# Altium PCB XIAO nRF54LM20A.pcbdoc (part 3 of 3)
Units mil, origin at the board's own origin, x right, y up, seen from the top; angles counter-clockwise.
Board outline 1393.7 x 1456.69 mil, 6 copper layers (Top Layer, L2.Cu, L3.Cu, L4.Cu, L5.Cu, Bottom Layer), stack 1.58 mil thick; 146 components, 0 nets, 519 pads, 402 vias.
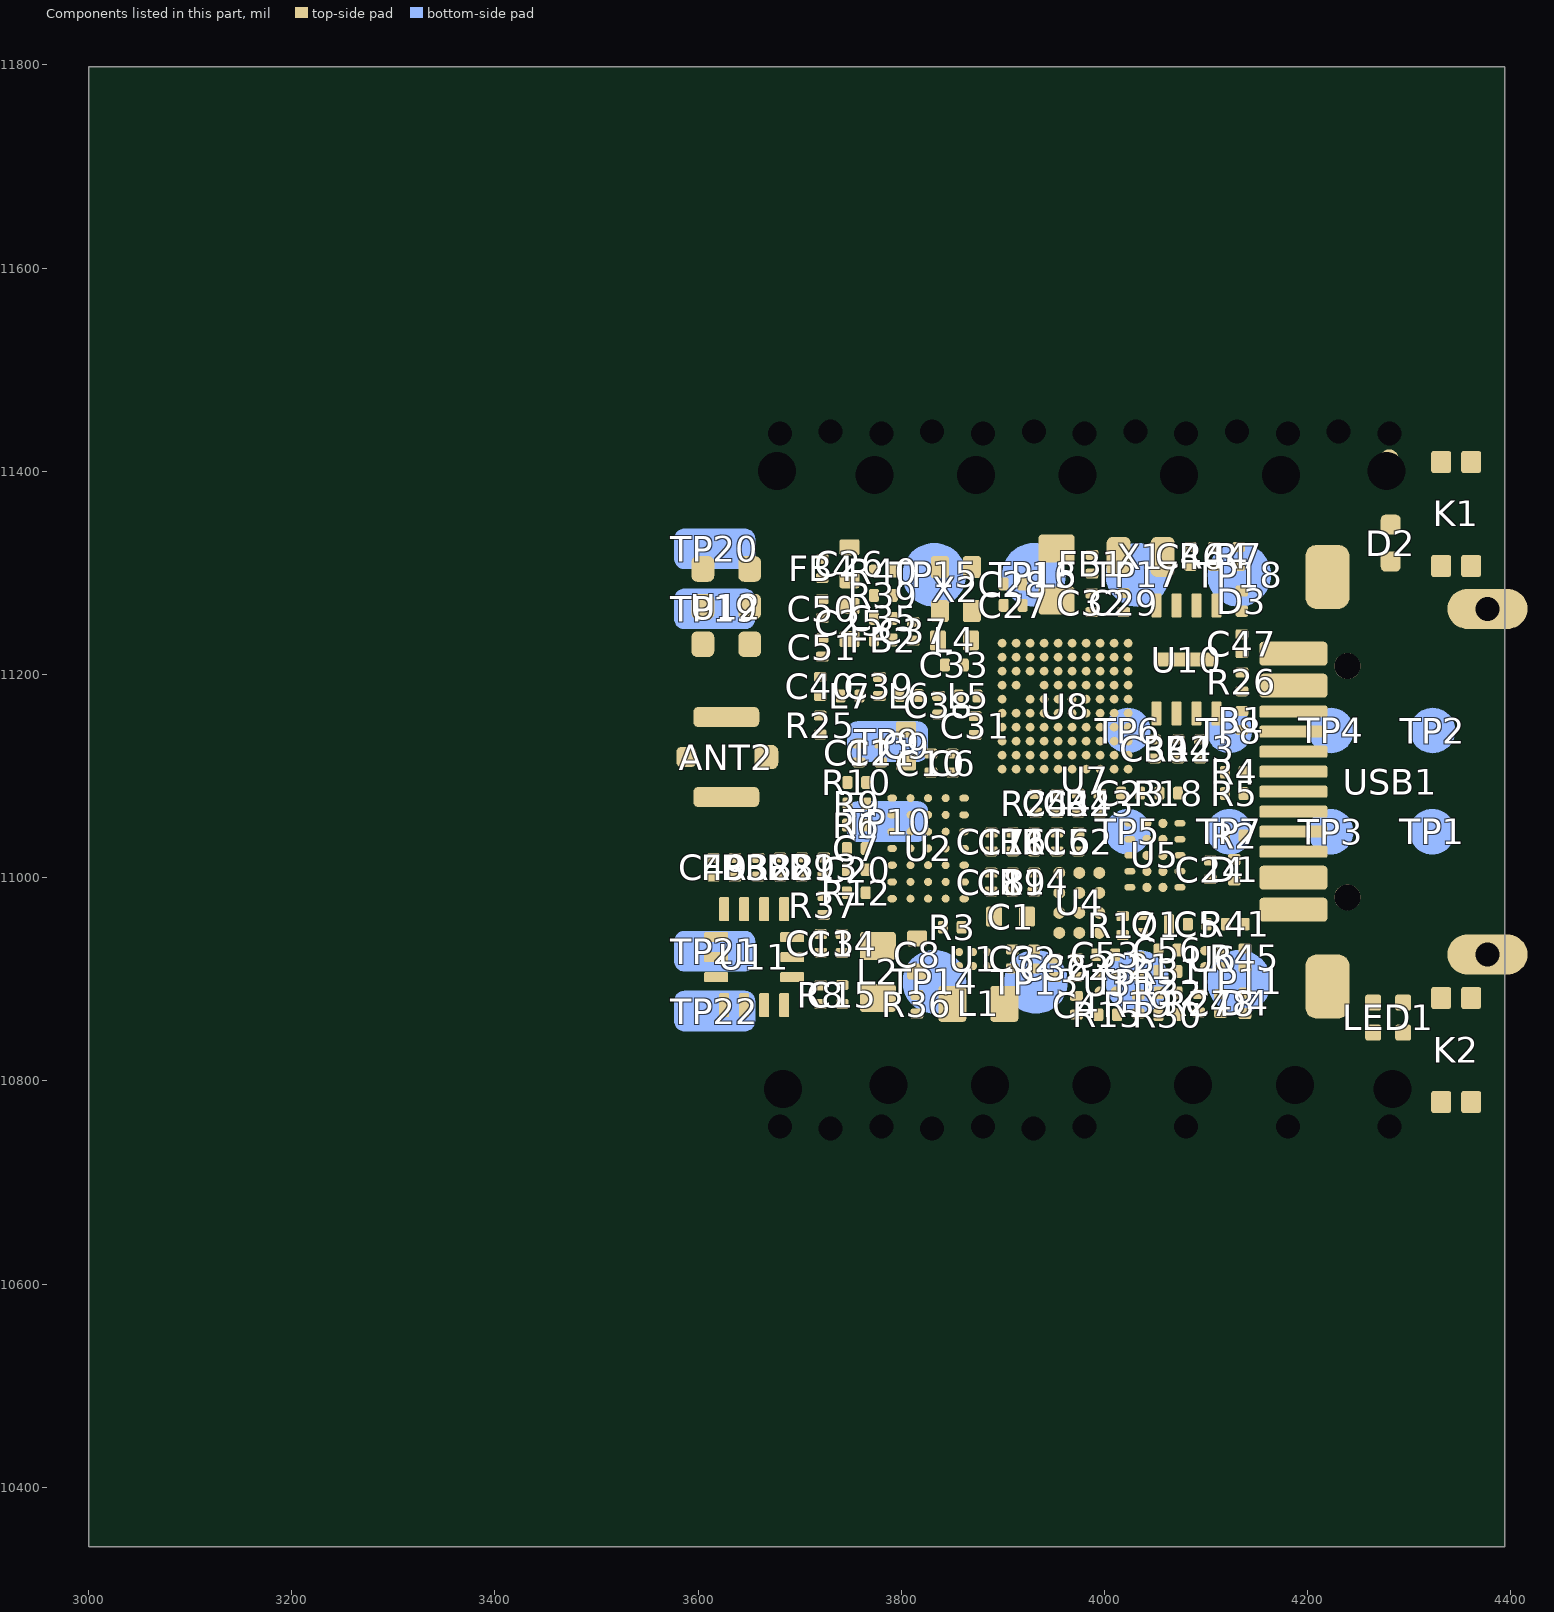
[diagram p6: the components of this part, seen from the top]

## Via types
v1: diameter 10, hole 6, Top Layer to Bottom Layer, 210 vias
v2: diameter 8, hole 4, Top Layer to L2.Cu, 76 vias
v3: diameter 10, hole 6, L3.Cu to L4.Cu, 47 vias
v4: diameter 8, hole 4, Top Layer to L3.Cu, 43 vias
v5: diameter 8, hole 4, L2.Cu to L3.Cu, 20 vias
v6: diameter 8, hole 4, L4.Cu to Bottom Layer, 6 vias

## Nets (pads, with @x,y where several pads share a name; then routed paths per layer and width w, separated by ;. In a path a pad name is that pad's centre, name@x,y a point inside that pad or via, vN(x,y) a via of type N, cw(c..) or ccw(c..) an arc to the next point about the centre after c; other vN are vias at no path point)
pads on no net: ANT2.1 ANT2.2 ANT2.3 ANT2.4 C1.1 C1.2 C2.1 C2.2 C3.1 C3.2 C4.1 C4.2 C5.1 C5.2 C6.1 C6.2 C7.1 C7.2 C8.1 C8.2 C9.1 C9.2 C10.1 C10.2 C11.1 C11.2 C12.1 C12.2 C13.1 C13.2 C14.1 C14.2 C15.1 C15.2 C16.1 C16.2 C17.1 C17.2 C18.1 C18.2 C19.1 C19.2 C20.1 C20.2 C21.1 C21.2 C22.1 C22.2 C23.1 C23.2 C24.1 C24.2 C25.1 C25.2 C26.1 C26.2 C27.1 C27.2 C28.1 C28.2 C29.1 C29.2 C30.1 C30.2 C31.1 C31.2 C32.1 C32.2 C33.1 C33.2 C34.1 C34.2 C35.1 C35.2 C36.1 C36.2 C37.1 C37.2 C38.1 C38.2 C39.1 C39.2 C40.1 C40.2 C46.1 C46.2 C47.1 C47.2 C48.1 C48.2 C49.1 C49.2 C50.1 C50.2 C51.1 C51.2 C52.1 C52.2 C53.1 C53.2 C54.1 C54.2 C56.1 C56.2 D1.1 D1.2 D2.1 D2.2 D3.1 D3.2 D4.1 D4.2 FB1.1 FB1.2 FB2.1 FB2.2 FB3.1 FB3.2 FB4.1 FB4.2 K1.1 K1.2 K1.3 K1.4 K2.1 K2.2 K2.3 K2.4 L1.1 L1.2 L2.1 L2.2 L3.1 L3.2 L4.1 L4.2 L5.1 L5.2 L6.1 L6.2 L7.1 L7.2 LED1.1 LED1.2 LED1.3 LED1.4 Q1.1 Q1.2 Q1.3 R1.1 R1.2 R2.1 R2.2 R3.1 R3.2 R4.1 R4.2 R5.1 R5.2 R6.1 R6.2 R7.1 R7.2 R8.1 R8.2 R9.1 R9.2 R10.1 R10.2 R11.1 R11.2 R12.1 R12.2 R13.1 R13.2 R14.1 R14.2 R15.1 R15.2 R16.1 R16.2 R17.1 R17.2 R18.1 R18.2 R19.1 R19.2 R23.1 R23.2 R24.1 R24.2 R25.1 R25.2 R26.1 R26.2 R27.1 R27.2 R28.1 R28.2 R29.1 R29.2 R30.1 R30.2 R31.1 R31.2 R32.1 R32.2 R36.1 R36.2 R37.1 R37.2 R38.1 R38.2 R39.1 R39.2 R40.1 R40.2 R41.1 R41.2 R42.1 R42.2 R43.1 R43.2 R44.1 R44.2 R45.1 R45.2 TP1.1 TP2.1 TP3.1 TP4.1 TP5.1 TP6.1 TP7.1 TP8.1 TP9.1 TP10.1 TP11.1 TP12.1 TP13.1 TP14.1 TP15.1 TP16.1 TP17.1 TP18.1 TP19.1 TP20.1 TP21.1 TP22.1 U1.A1 U1.A2 U1.B1 U1.B2 U1.C1 U1.C2 U2.A1 U2.A2 U2.A3 U2.A4 U2.A5 U2.A6 U2.A7 U2.B1 U2.B2 U2.B3 U2.B4 U2.B5 U2.B6 U2.B7 U2.C1 U2.C2 U2.C3 U2.C4 U2.C5 U2.C6 U2.C7 U2.D1 U2.D2 U2.D3 U2.D4 U2.D5 U2.D6 U2.D7 U2.E1 U2.E2 U2.E3 U2.E4 U2.E5 U2.E6 U2.E7 U3.A1 U3.A2 U3.B1 U3.B2 U4.A1 U4.A2 U4.A3 U4.B1 U4.B2 U4.B3 U4.C1 U4.C2 U4.C3 U4.D1 U4.D2 U4.D3 U5.A1 U5.A2 U5.A3 U5.A4 U5.B1 U5.B2 U5.B3 U5.B4 U5.C1 U5.C2 U5.C3 U5.C4 U5.D1 U5.D2 U5.D3 U5.D4 U5.E1 U5.E2 U5.E3 U5.E4 U6.A1 U6.A2 U6.B1 U6.B2 U7.1 U7.2 U7.3 U7.4 U7.5 U7.6 U7.7 U7.8 U7.9 U7.10 U7.11 U7.12 U7.13 U7.14 U7.15 U7.16 U7.17 U7.18 U7.19 U7.20 U7.21 U7.22 U7.23 U8.A1 U8.A2 U8.A3 U8.A4 U8.A5 U8.A6 U8.A7 U8.A8 U8.A9 U8.A10 U8.B1 U8.B2 U8.B3 U8.B4 U8.B5 U8.B6 U8.B7 U8.B8 U8.B9 U8.B10 U8.C1 U8.C2 U8.C3 U8.C4 U8.C5 U8.C6 U8.C7 U8.C8 U8.C9 U8.C10 U8.D1 U8.D2 U8.D4 U8.D5 U8.D6 U8.D7 U8.D8 U8.D9 U8.D10 U8.E1 U8.E3 U8.E4 U8.E5 U8.E6 U8.E7 U8.E8 U8.E9 U8.E10 U8.F1 U8.F2 U8.F3 U8.F4 U8.F5 U8.F6 U8.F7 U8.F8 U8.F9 U8.F10 U8.G1 U8.G2 U8.G3 U8.G4 U8.G5 U8.G6 U8.G7 U8.G8 U8.G9 U8.G10 U8.H1 U8.H2 U8.H3 U8.H4 U8.H5 U8.H6 U8.H7 U8.H8 U8.H9 U8.H10 U8.J1 U8.J2 U8.J3 U8.J4 U8.J5 U8.J6 U8.J7 U8.J8 U8.J9 U8.J10 U8.K1 U8.K2 U8.K3 U8.K4 U8.K5 U8.K6 U8.K7 U8.K8 U8.K9 U8.K10 U10.1 U10.2 U10.3 U10.4 U10.5 U10.6 U10.7 U10.8 U10.9 U11.1 U11.2 U11.3 U11.4 U11.5 U11.6 U11.7 U11.8 U11.9 U11.10 U11.11 U11.12 U11.13 U11.14 U12.1 U12.2 U12.3 U12.4 U12.5 U12.6 USB1. USB1.A1B12 USB1.A4B9 USB1.A5 USB1.A6 USB1.A7 USB1.A8 USB1.B1A12 USB1.B4A9 USB1.B5 USB1.B6 USB1.B7 USB1.B8 USB1.S1 USB1.S2 USB1.S3 USB1.S4 X1.1 X1.2 X2.1 X2.2 X2.3 X2.4
copper on no net: | length 36443.2
  Top Layer w3: 6910.97,7346.9 6910.97,7361.13 6915.5,7365.66 6930.57,7365.66 6943.82,7378.91 6944.28,7378.91 ; 6965.92,7379.14 6988.46,7356.6 6988.46,7325.12 6982.69,7319.34 6977.9,7319.34 ; 6977.9,7299.66 6991.5,7299.66 6994.5,7302.66 6994.5,7372.03 6987.36,7379.17 ; 7009,7341.41 7011.55,7341.41 7017.8,7347.66 ; 7009,7397.91 7009,7406.66 7020.5,7418.16 7059,7418.16 7064.06,7423.22 7076.21,7423.22 ; 7030.5,7349.66 7040,7349.66 7050.25,7359.91 7050.25,7363.16 7050.25,7364.66 7075.82,7390.23 7076.21,7390.23 ; 7035,7645.16 7045.55,7655.71 7058.41,7655.71 ; 7035.9,7672.66 7037.4,7671.16 ; 7037.5,7671.16 7045.97,7679.63 7058.41,7679.63 ; 7050.39,7429.66 7052.32,7429.66 7053.96,7431.3 7086.23,7431.3 7094.32,7423.22 ; 7050.75,7450.66 7050.75,7448.63 7059.66,7439.71 7076.21,7439.71 ; 7050.75,7471.66 7050.75,7469.63 7064.17,7456.21 7076.21,7456.21 ; 7076.91,7655.71 7077.45,7655.71 7089,7644.16 ; 7100.64,7262.59 7108.16,7262.59 7136.51,7290.94 7142.22,7290.94 ; 7123.25,7683.56 7123.25,7681.91 7143,7662.16 7161.25,7662.16 7171.5,7651.91 7171.5,7635.56 7198.28,7608.78 ; 7142.22,7304.72 7142.22,7326.63 7144.75,7329.16 ; 7147.07,7439.71 7152.94,7439.71 ; 7154.75,7640.25 7170.5,7624.5 7170.5,7602.16 7177.66,7595 7184.5,7595 ; 7198.28,7539.88 7200,7541.6 7200,7555.32 7201.06,7556.38 ; 7209.36,7578.84 7211.46,7578.84 7212.06,7579.44 7212.06,7581.22 ; 7217.5,7460.41 7217.5,7466.26 7224.51,7473.27 7224.51,7473.45 7225.9,7472.06 ; 7219,7567.16 7219.28,7567.44 7225.84,7567.44 ; 7280.12,7323.6 7290.57,7334.05 7290.57,7373.22 7301.5,7384.16 7310.26,7384.16 ; 7296.03,7266.09 7315.13,7266.09 7318.52,7262.69 7317.41,7262.69 7297.65,7242.94 ; 7303.21,7340.03 7304.2,7339.05 7323.2,7339.05 7327,7342.85 7327,7368.41 ; 7308.52,7539.88 7311.22,7539.88 7328.5,7557.16 7352,7557.16 7355.66,7553.5 7355.66,7540.01 7356.16,7539.51 ; 7308.52,7553.66 7316,7553.66 7326,7563.66 7367.5,7563.66 7375.34,7555.81 7375.34,7540.01 7375.84,7539.51 7375.34,7539.01 7375.34,7518.07 7379.5,7513.91 ; 7308.52,7567.44 7318.28,7567.44 7329,7578.16 7329,7600.16 7341,7612.16 7370.49,7612.16 7370.69,7612.36 7389.2,7612.36 7395.03,7618.19 7395.03,7645.31 7395.53,7645.81 ; 7308.52,7581.22 7318.02,7581.22 7322.96,7586.16 7322.96,7603.12 7338,7618.16 7368,7618.16 7375.34,7625.5 7375.34,7645.31 7375.84,7645.81 ; 7308.52,7595 7316.92,7603.4 7316.92,7605.62 7335.76,7624.46 7351.4,7624.46 7356.16,7629.22 7356.16,7645.81 7356.16,7652.81 7388.25,7684.91 7393.5,7684.91 ; 7320.25,7461.16 7339.25,7461.16 7342.75,7457.65 7342.75,7431.4 ; 7331.5,7235.66 7338.5,7242.66 7338.5,7243.16 ; 7336.47,7539.51 7335.97,7539.01 7335.97,7533.19 7355.25,7513.91 7358,7513.91 ; 7348.47,7357.26 7348.47,7353.78 7348.8,7353.45 7348.8,7332.16 ; 7357,7243.16 7362.5,7248.66 ; 7359.5,7431.4 7359.5,7441.16 ; 7378,7263.66 7378.25,7263.41 7399.5,7263.41 7400.28,7264.19 7423.5,7264.19 7423.5,7265.66 7447.5,7289.66 7469.5,7311.66 7564.57,7311.66 7616.69,7259.54 7646.21,7259.54 ; 7399.87,7290.28 7402.63,7290.28 7420.75,7308.41 7423.5,7308.41 7423.5,7331.91 7423.25,7332.16 ; 7417.5,7703.41 7432.5,7688.41 7432.5,7681.66 7432.5,7643.16 7443.5,7632.16 7553.5,7632.16 7586,7664.66 7586,7706.37 7567,7725.37 ; 7420.5,7541.91 7421.15,7541.26 7471.26,7541.26 ; 7420.5,7579.91 7420.5,7597.66 7411,7597.66 7405,7603.66 7405,7625.16 7419.97,7640.13 7420.5,7640.13 7421.03,7640.13 7437,7624.16 7556.5,7624.16 7616.69,7684.34 7616.69,7684.73 7646.21,7684.73 ; 7420.5,7703.41 7422.25,7703.41 ; 7422.25,7419.16 7426.25,7423.15 7471.26,7423.15 ; 7549.5,7688.66 7549.79,7688.95 7567,7688.95 ; 7549.74,7254.92 7549.74,7274.49
  Top Layer w4: 7211.76,7610.06 7212.06,7609.76
  Top Layer w5.59: 4136.95,11082.7 cw(c4141.46,11078.2) 4141.46,11084.57 ; 4136.95,11103.7 cw(c4138.28,11102.37) 4138.28,11104.26 ; 7359.5,7399.91 7365.01,7399.91 7367.09,7401.98 7376.79,7401.98 7388.1,7413.3 7388.1,7460.43 7393.03,7465.36 7397.67,7465.36 7402.37,7460.66 7403.75,7460.66 ; 7359.5,7415.65 7365.01,7415.65 7367.09,7413.57 7371.99,7413.57 7376.51,7418.1 7376.51,7465.16 7388.31,7476.95 7397.67,7476.95 7402.37,7481.66 7403.75,7481.66 ; 7423.58,7482.21 7471.26,7482.21 7507.45,7482.21 7512,7477.66 7512,7447.66 7507.18,7442.84 7471.26,7442.84 ; 7426.76,7462.52 7471.26,7462.52
  Top Layer w6: 7050.25,7385.66 7071.32,7406.72 7076.21,7406.72 ; 7070.5,7353.66 7074.08,7357.23 7076.21,7357.23 ; 7147.07,7406.72 7149.83,7406.72 7173.68,7382.87 ; 7236.5,7298.91 7236.66,7298.91 7255.16,7280.41 7257.5,7280.41 ; 7359.5,7384.16 7366,7384.16 7373.75,7376.41 7392,7376.41
  Top Layer w6.16: 3667.07,11118.7 ccw(c3667.07,11193.26) 3719.79,11140.54 ; 3758.7,11178.7 cw(c3759.91,11177.5) 3759.91,11179.2 ; 3778.46,11178.89 cw(c3779.21,11178.14) 3779.21,11179.2 ; 3816.95,11179.2 ccw(c3818.16,11180.41) 3818.16,11178.7 ; 3836.7,11178.96 ccw(c3837.31,11179.57) 3837.31,11178.7 ; 3874.95,11178.7 ccw(c3882.19,11185.95) 3882.19,11175.7 ; 7005.09,7518.49 7005.5,7518.91 ; 7005.5,7537.41 7005.5,7556.91 7005.75,7556.66 7025.5,7556.66 ; 7045.21,7557.16 7083.75,7557.16 7064.51,7557.16 ; 7103.46,7556.66 7141.75,7556.66 7122.61,7556.66 ; 7167.49,7553.66 7184.5,7553.66
  Top Layer w8: 6920.5,7378.91 6924.25,7378.91 6942.75,7397.41 6944.28,7397.41 6965.69,7397.41 6965.92,7397.64 6987.33,7397.64 ; 7009,7379.41 7012.25,7379.41 7028.5,7363.16 7031.75,7363.16 7031.75,7365.58 7050.25,7384.08 7050.25,7385.66 ; 7091,7350.16 7094.32,7353.47 7094.32,7357.23 ; 7094.32,7439.71 7094.32,7456.21 ; 7146.75,7587.27 7172.32,7587.27 7178.38,7581.22 7184.5,7581.22 ; 7158,7517.16 7162.84,7512.32 7184.5,7512.32 ; 7238.54,7460.25 7238.54,7464.69 7253.4,7479.56 7253.4,7484.76 ; 7253.4,7608.78 7253.4,7619.8 7272.79,7639.19 ; 7267.18,7484.76 7267.18,7476.83 7259.5,7469.16 7259.5,7460.64 7259.4,7460.55 7280.53,7460.55 7280.66,7460.41 ; 7267.18,7608.78 7267.18,7616.6 7268.96,7618.38 ; 7272.84,7677.19 7276.28,7677.19 7288.5,7664.97 7288.5,7631.16 7280.96,7623.61 7280.96,7608.78 ; 7294.74,7608.78 7294.74,7615.89 7304,7625.16 7304,7639.41 ; 7296.03,7281.84 7318.32,7281.84 7319,7281.16 ; 7301.75,7461.16 7308.52,7467.93 7308.52,7484.76 7323.85,7484.76 7332.25,7493.16 7334.8,7493.16 7335,7492.96 ; 7304,7657.91 7310.3,7657.91 7319,7649.21 7319,7624.16 7308.52,7613.67 7308.52,7608.78 ; 7308.52,7526.1 7323.21,7526.1 7334.5,7514.81 7334.5,7513.91 ; 7336.47,7645.81 7336.47,7660.13 7343,7666.66 7354.87,7666.66 7370,7681.79 7370,7684.91 ; 7337.42,7513.78 7355.79,7495.41 7358,7495.41 7379.5,7495.41 ; 7370,7684.16 7370.83,7684.16 7390.08,7703.41 7393.5,7703.41
  Top Layer w10: 6898,7323.16 6901.81,7319.34 6903.1,7319.34 6895.5,7326.94 6895.5,7373.23 6899.5,7377.23 6899.5,7378.97 6901.24,7378.97 6901.4,7379.13 6920.28,7379.13 6920.5,7378.91 ; 6936.03,7607.77 6942.17,7613.91 7005.5,7613.91 ; 7005,7297.66 7006,7298.66 7006,7303.36 7007.2,7304.56 7007.79,7303.97 7017.19,7303.97 7017.5,7303.66 7017.69,7303.85 7027,7303.85 7027,7299.66 7025,7297.66 ; 7005.88,7272.03 7006.08,7272.23 7006.08,7282.66 ; 7007.5,7613.91 7007.5,7633.41 ; 7027.12,7272.15 7027.99,7272.15 7032.5,7276.66 ; 7173.5,7403.66 7173.73,7403.89 7188,7403.89 ; 7173.68,7382.87 7194.68,7382.87 ; 7182.5,7698.66 7204.59,7676.57 7204.59,7666.94 7204.59,7645.94 7212.06,7638.47 7212.06,7608.78 7225.84,7608.78 ; 7186.09,7645.94 7186.09,7666.94 ; 7194.92,7403.89 7188,7403.89 ; 7215.92,7382.89 7215.92,7403.88 7188.01,7403.88 ; 7238.5,7617.16 7239.62,7616.04 7239.62,7608.78 ; 7240.16,7254.06 7251.09,7243.13 7257.6,7243.13 ; 7260.44,7343.29 7260.44,7362.97 ; 7260.44,7382.66 7260.44,7400.09 7261.72,7401.38 ; 7280.28,7281.84 7278.82,7281.84 7275.75,7284.91 ; 7275.75,7284.91 7275.75,7300.91 7277,7302.16 7273.75,7298.91 7257.5,7298.91 7261.75,7298.91 7275.75,7284.91
  Top Layer w12: 7005,7297.66 7025,7297.66 ; 7006,7324.16 7025.5,7324.16 7027.5,7326.16 7039.5,7338.16 7050.5,7338.16 7055,7338.16 7070.5,7353.66 ; 7056.11,7259.55 7062.2,7259.55 7049.61,7259.55 7032.5,7276.66 7032.5,7286.16 ; 7058.25,7611.91 7058.25,7632.96 7058.41,7633.13 ; 7062.2,7310.73 7078.5,7327.03 7078.5,7337.66 7091,7350.16 ; 7076.75,7611.91 7077.5,7611.15 7097,7611.15 7097.25,7611.41 7121.26,7611.41 7121.26,7594.26 7128.25,7587.27 ; 7146.75,7587.27 7147,7587.52 7147,7599.16 7153.74,7605.9 7153.74,7611.41 ; 7238.14,7650.61 7238.14,7617.52 7238.5,7617.16 ; 7238.14,7701.79 7266.74,7701.79 7272.84,7695.69 ; 7025,7297.66 7032.5,7290.16 7032.5,7286.16 ; 7025,7297.66 7032,7297.66 7032.5,7297.16 7032.5,7286.16
  L2.Cu w3: 6890.5,7681.66 6899.6,7690.76 6941.44,7690.76 6949.5,7682.7 6949.5,7657.16 7008.5,7598.16 7193.5,7598.16 7207.5,7584.16 7207.5,7580.7 7209.36,7578.84 ; 6928.5,7304.66 6928.5,7305.16 7019.5,7396.16 7084,7396.16 7094.5,7406.66 ; 6937,7681.16 6937,7654.66 6999.5,7592.16 7187.34,7592.16 7198.28,7581.22 ; 6971.5,7279.97 6971.5,7321.16 6996,7345.66 7015.8,7345.66 7017.8,7347.66 ; 7023.5,7648.66 7024,7648.66 7030.04,7654.7 7097.96,7654.7 7119.5,7633.16 7196.5,7633.16 7225.84,7603.82 7225.84,7595 ; 7023.5,7661.16 7150,7661.16 7153,7658.16 7188.49,7658.16 7239.62,7607.03 7239.62,7595 ; 7028,7613.16 7167.5,7613.16 7174,7619.66 7185.99,7619.66 7209.46,7596.19 7209.46,7590.76 7225.06,7575.16 7231.9,7575.16 7239.62,7567.44 ; 7032.99,7583.15 7035.5,7585.66 7179,7585.66 7197.5,7567.16 7219,7567.16 ; 7033,7625.66 7041.5,7625.66 7046.5,7620.66 7161.5,7620.66 7168,7627.16 7189,7627.16 7215.5,7600.66 7215.5,7593.26 7227.54,7581.22 7239.62,7581.22 ; 7095,7451.16 7227.8,7451.16 7258.08,7481.43 7258.08,7485.68 7267,7494.6 7267,7498.66 ; 7095.5,7463.66 7103,7463.66 7108,7458.66 7226.1,7458.66 7251.3,7483.86 7251.3,7496.46 7253.5,7498.66 ; 7101,7493.16 7146.5,7493.16 7173,7466.66 7206.08,7466.66 7226,7486.58 7226,7498.66 ; 7127,7518.66 7137,7528.66 7163,7528.66 7169,7534.66 7204.5,7534.66 7206.5,7532.66 7218.5,7532.66 7226,7540.16 ; 7140.75,7519.41 7141.45,7519.41 7142.7,7518.16 7142.7,7517.96 7147.5,7513.16 7147.5,7512.81 7153.65,7506.66 7162.35,7506.66 7163.85,7508.16 7188.44,7508.16 7197.94,7498.66 7198.5,7498.66 ; 7155.46,7496.2 7166.5,7485.16 7198.5,7485.16 ; 7225.9,7472.06 7225.23,7472.73 7226.27,7472.73 7239.62,7486.08 7239.62,7498.54 ; 7253.4,7581.22 7250.5,7584.11 7250.5,7656.16 7261.46,7667.12 7285.46,7667.12 7298,7679.66 7298,7693.16 ; 7265.66,7174.1 7265.66,7245.5 7229,7282.16 7229,7359.81 7228.75,7360.06 7228.75,7368.76 7229,7369.01 7229,7442.16 7266.05,7479.21 7266.05,7483.81 7280.9,7498.66 7281,7498.66 ; 7265.66,7774.1 7265.66,7730.5 7291.5,7704.66 7366,7704.66 7391.5,7679.16 7391.5,7558.16 7356.96,7523.62 7319.81,7523.62 7308.52,7512.32 ; 7267.18,7567.44 7282.6,7582.86 7325.3,7582.86 7335.5,7572.66 ; 7267.18,7581.22 7258,7590.39 7258,7637.65 7268.5,7648.15 7279.99,7648.15 7325.5,7693.66 7342,7693.66 ; 7267.18,7595 7277.24,7605.06 7286.41,7605.06 7308.5,7627.15 7308.5,7628.51 7314.65,7634.66 7323.35,7634.66 7324.31,7633.7 7370.46,7633.7 7377.5,7626.66 ; 7267.5,7553.66 7286.5,7572.66 7308.5,7572.66 ; 7280.12,7362.97 7285.81,7368.66 7342.5,7368.66 ; 7280.5,7343.66 7270.4,7353.76 7270.4,7367.56 7279.5,7376.66 7335.5,7376.66 7339.62,7380.78 ; 7280.96,7595 7308.34,7595 7327.5,7614.16 7377.5,7614.16 ; 7281,7386.16 7284.5,7389.66 7345,7389.66 7359,7375.66 7359,7366.16 ; 7281,7484.66 7290.5,7475.16 7363.52,7475.16 7480.35,7591.99 7481.71,7591.99 7565.66,7675.93 7565.66,7774.1 ; 7281,7526.16 7304.2,7549.36 7342.2,7549.36 7358.5,7565.66 7358.5,7602.16 7360.14,7603.79 7360.82,7603.79 ; 7281,7540.16 7296.7,7555.86 7333.2,7555.86 7345,7567.66 7345,7589.76 7342.5,7592.26 ; 7281,7553.66 7290.3,7562.96 7312.8,7562.96 7322,7572.16 ; 7294.5,7484.66 7296.9,7482.26 7358.6,7482.26 7465.66,7589.31 7465.66,7774.1 ; 7294.74,7526.1 7308.3,7539.66 7337,7539.66 ; 7295,7512.16 7299.02,7516.17 ; 7299.02,7516.25 7304.58,7521.82 ; 7304.66,7521.82 7312.9,7530.06 7341.9,7530.06 7366,7554.16 7366,7594.16 7373.7,7601.86 ; 7308.5,7498.66 7313.5,7503.66 7348.5,7503.66 7399.5,7554.66 7399.5,7740.26 7365.66,7774.1 ; 7332,7603.04 7332,7602.81 7342.5,7592.31 ; 7343,7415.66 7355.26,7427.92 7358.26,7427.92 ; 7358,7285.66 7364.4,7285.66 7375.5,7274.56 7549.8,7274.56 ; 7359,7264.16 7365.4,7264.16 7375.2,7254.36 7520.8,7254.36 7549.5,7225.66 ; 7362.5,7248.66 7356.3,7248.66 7349.8,7255.16 7349.8,7269.06 7354,7273.26 7368.31,7273.26 7377.81,7263.76 7570.9,7263.76 7579.5,7255.16
  L2.Cu w8: 7050.25,7406.66 7077.5,7406.66 7094.06,7423.22 7111.64,7423.22 ; 7101,7315.66 7111,7305.66 7111,7253.66 7101.5,7244.16 ; 7319,7281.16 7319,7266.16 7349.4,7235.76 7371.1,7235.76 7378.5,7243.16 7509.5,7243.16 7539.5,7213.16 7567,7213.16 7580,7226.16 ; 7319.5,7243.66 7304.5,7258.66 7304.5,7284.66 7321,7301.16 7352.5,7301.16 7359,7307.66
  L2.Cu w10: 6902.5,7319.16 6902.5,7260.16 6911,7251.66 ; 7005,7632.66 7005,7672.16 ; 7096,7280.66 7091,7275.66 7009.51,7275.66 7005.88,7272.03 7005.13,7272.03 6983.5,7293.66 6983.5,7314.66 7002.5,7333.66 7020,7333.66 7027.5,7326.16 7025.5,7324.16 7006,7324.16 6992.96,7311.12 6992.96,7296.78 7006.08,7283.66 7006.08,7282.66 7007.08,7283.66 7090,7283.66 7096,7289.66 ; 7128.96,7406.72 7132.03,7403.66 7173.5,7403.66 ; 7277,7302.16 7277,7326.16 7260.5,7342.66 7260.5,7363.16 7260.5,7382.16 7239,7403.66 7238.5,7403.66 7238.5,7410.66 7244.5,7416.66 7313.5,7416.66 7357.75,7460.91 7357.75,7461.16 ; 7420.5,7660.16 7434,7660.16 7448.5,7645.66
  L2.Cu w12: 7051,7385.16 7051,7374.16 7067.5,7357.66 7101.5,7357.66 7111.5,7367.66 7111.5,7373.16
  L3.Cu w3: 6944,7364.16 6944,7378.16 6944.5,7378.66 ; 6961,7388.16 6961,7384.66 6966.5,7379.16 ; 6978,7386.26 6980.4,7386.26 6986,7380.66 6986,7379.16 ; 7017.8,7347.66 7017.8,7347.36 7025.3,7339.86 7035.2,7339.86 7041.46,7346.12 7041.46,7461.62 7057.5,7477.66 7057.5,7558.66 7033.01,7583.15 ; 7020.5,7418.16 7012,7426.66 7012,7637.16 7023.5,7648.66 ; 7023.5,7661.16 7020.5,7658.16 7019.56,7658.16 7014,7652.59 7014,7651.66 7005.5,7643.16 7005.5,7419.16 7015.5,7409.16 7015.5,7364.66 7030.5,7349.66 ; 7028,7613.16 7028,7600.16 7064.46,7563.7 7064.46,7474.62 7055.5,7465.66 7055.5,7396.16 7060.5,7391.16 7060.5,7315.16 7067.5,7308.16 ; 7033,7625.66 7036.54,7622.12 7036.54,7601.16 7070.5,7567.2 7070.5,7470.16 7062.5,7462.16 7062.5,7397.7 7066.5,7393.7 7066.5,7326.16 7084.5,7308.16 7084.5,7307.66 ; 7047,7605.66 7053.54,7599.12 7328.08,7599.12 7332,7603.04 ; 7065.66,7774.1 7065.66,7660.81 7046.5,7641.66 7046.5,7621.46 7059.8,7608.16 7149.5,7608.16 7160.5,7619.16 7198,7619.16 7209,7608.16 7264.33,7608.16 7264.61,7607.88 7273.31,7607.88 7273.58,7608.16 7323.68,7608.16 7328.06,7612.54 7352.72,7612.54 7358.5,7606.76 7358.5,7605.16 7359.86,7603.79 7360.82,7603.79 ; 7073.5,7412.66 7075.7,7412.66 7111,7447.96 7111,7534.35 7128.51,7551.86 7165.8,7551.86 7170.94,7546.72 7200.74,7546.72 7206.3,7541.16 7212.06,7541.16 ; 7076,7373.66 7076,7361.16 7081.5,7355.66 ; 7077,7680.66 7086.5,7680.66 ; 7081.5,7451.16 7095,7451.16 ; 7084.27,7626.58 7084.5,7626.81 7084.5,7639.66 7089,7644.16 ; 7085.5,7463.66 7095.5,7463.66 ; 7090.97,7411.69 7090.97,7415.12 7117,7441.16 7117,7522.16 7122.5,7527.66 ; 7094.5,7363.66 7094.5,7373.66 ; 7097,7502.66 7101,7498.66 7101,7493.16 ; 7115.66,7124.1 7112.5,7127.26 7112.5,7339.66 7124.5,7351.66 7124.5,7383.16 7118,7389.66 7118,7432.16 7123.46,7437.62 7123.46,7515.12 7127,7518.66 ; 7122.56,7527.66 7123.06,7528.16 7130.94,7528.16 7131.44,7527.66 7161.98,7527.66 7174.8,7540.48 7196.68,7540.48 7212,7525.16 7212,7523.66 ; 7125,7299.96 7125,7302.66 7142,7319.66 7210,7319.66 7217,7312.66 7245.5,7312.66 7250,7317.16 7250,7349.16 7257.04,7356.2 7257.04,7381.12 7229.5,7408.66 7229.5,7508.16 7225.5,7512.16 ; 7126,7736.16 7135,7745.16 7198.5,7745.16 7215.66,7762.31 7215.66,7824.1 ; 7136.5,7510.16 7142.7,7516.36 7142.7,7518.16 ; 7140,7721.66 7156.5,7738.16 7271,7738.16 7300,7709.16 7349.5,7709.16 7415.66,7775.31 7415.66,7824.1 ; 7150,7506.16 7155,7501.16 7155,7496.68 7155.46,7496.22 ; 7172,7677.16 7172.5,7677.16 7183.5,7688.16 7279.5,7688.16 7347.5,7620.16 7358,7620.16 7370.93,7607.22 7370.93,7603.33 7372.4,7601.86 7373.7,7601.86 ; 7183.5,7489.16 7183.5,7497.66 7184.5,7498.66 ; 7184.25,7523.94 7184.25,7511.74 7180.67,7508.16 7180.56,7508.16 7175,7502.59 7175,7502.48 7173,7500.48 7173,7479.66 7184,7468.66 7184,7419.31 7182,7417.31 7182,7380.66 7188.8,7373.86 7229.8,7373.86 7239.25,7364.41 ; 7198.5,7512.16 7193,7506.66 7193,7406.66 7205,7394.66 7205,7394.16 ; 7198.6,7525.06 7198.6,7526.06 7191,7533.66 7177.43,7533.66 7171.65,7527.88 7171.65,7514.49 7164.96,7507.8 7164.96,7429.97 7163,7428.01 7163,7379.16 7189.5,7352.66 7242.5,7352.66 7251,7361.16 7251,7372.16 7241,7382.16 ; 7201.06,7556.38 7201.23,7556.38 7235,7590.16 7413,7590.16 7420.5,7597.66 ; 7202.5,7496.11 7205.04,7498.66 7212,7498.66 ; 7204.36,7461.94 7202.5,7463.8 7202.5,7476.01 7208.65,7482.16 7209.56,7482.16 7212.03,7484.63 ; 7211.5,7510.86 7212.3,7511.66 7212.56,7511.66 7221.5,7502.72 7221.5,7488.59 ; 7212.06,7553.66 7212.06,7554.02 7241.5,7583.46 7284.2,7583.46 7417.5,7450.16 7417.5,7375.66 7447.5,7345.66 7447.5,7289.66 ; 7213,7471.66 7221.5,7480.16 7221.5,7480.67 ; 7221.53,7480.69 7221.53,7488.56 ; 7226,7324.66 7226.5,7324.16 7239.3,7324.16 ; 7226,7553.66 7229.12,7556.78 7229.12,7559.18 7247.3,7577.36 7267.84,7577.36 7324.5,7520.7 7324.5,7485.96 7340,7470.46 7340,7432.74 7361.7,7411.04 7361.7,7391.04 7419.8,7332.94 7419.8,7225.96 7418.5,7224.66 ; 7230.5,7337.16 7234.5,7337.16 7240.5,7343.16 ; 7236.5,7301.66 7257.5,7301.66 7271.5,7315.66 7271.5,7342.16 7264,7349.66 7264,7383.36 7239.5,7407.86 7239.5,7512.16 ; 7253.4,7567.44 7269.22,7567.44 7318.5,7518.16 7318.5,7481.66 7332.5,7467.66 7332.5,7431.66 7352.46,7411.7 7352.56,7411.7 7353.25,7411.01 7353.25,7390.95 7411.64,7332.56 7411.64,7291.3 7408.5,7288.16 ; 7253.5,7512.16 7253.5,7467.66 7248.9,7463.06 7248.9,7429.04 7281,7396.94 7281,7333.36 7301.65,7312.71 ; 7267,7512.16 7267,7469.16 7268.94,7467.22 7268.94,7419.72 7298.5,7390.16 7298.5,7332.15 7320,7310.65 7320,7288.66 7315,7283.66 ; 7267,7526.16 7270.92,7526.16 7275.31,7530.55 ; 7267.5,7539.66 7269.1,7541.26 7283.4,7541.26 7309.54,7515.12 7309.54,7409.62 7343.46,7375.7 7359.96,7375.7 7398,7337.66 7398,7300.16 7398.14,7300.02 7400.33,7300.02 ; 7281,7512.16 7281,7476.66 7295,7462.66 7295,7406.16 7307.5,7393.66 7307.5,7358.07 7348.3,7317.27 7348.3,7221.46 7347.5,7220.66 ; 7295,7498.66 7295,7473.66 7303.5,7465.16 7303.5,7406.2 7340.04,7369.66 7355.99,7369.66 7388.5,7337.15 7388.5,7271.16 7388.5,7238.66 7388.5,7229.16 ; 7308.5,7572.66 7312.5,7568.66 7312.5,7568.22 7318.06,7562.66 7318.5,7562.66 7427,7454.16 7427,7386.06 7436.26,7376.8 7436.42,7376.8 ; 7322,7572.16 7437.5,7456.66 7437.5,7393.66 7450.5,7380.66 7450.5,7359.16 ; 7326.38,7265.28 7326.38,7279.24 7332.38,7285.24 7335.86,7285.24 7338.33,7287.71 ; 7331.5,7235.66 7331.5,7245.66 ; 7335.5,7572.66 7447.5,7460.66 7447.5,7395.31 7461.7,7381.11 7461.7,7273.46 7469.5,7265.66 ; 7337.42,7274.74 7338.5,7273.66 7338.5,7264.49 ; 7358.26,7427.92 7364.52,7421.66 7385.5,7421.66 ; 7377.5,7614.16 7423.5,7614.16 7457,7580.66 7457,7400.66 7470.5,7387.16 ; 7377.5,7626.66 7423,7626.66 7466,7583.66 7466,7406.86 7482.5,7390.36 7482.5,7256.66
  L3.Cu w5.59: 7486.5,7462.66 7486.5,7501.66
  L3.Cu w8: 7420.5,7684.66 7420.5,7642.33 7481.5,7581.33 7481.5,7536.16 7481,7535.66
  L3.Cu w10: 6922.5,7397.66 6922.5,7398.16 6933.5,7409.16 6979,7409.16 6988.5,7418.66 6994.5,7418.66 6994,7419.16 6994,7681.66 7005.5,7693.16 ; 6988,7397.66 7003,7382.66 7003,7359.66 ; 7357.75,7461.16 7385.5,7461.16 7404.5,7442.16 7404.5,7388.91 7392,7376.41
  L3.Cu w12: 7058.41,7633.13 7087.4,7662.11 7241.96,7662.11 7256.5,7676.66 7272.5,7676.66
  L4.Cu w3: 6944,7364.16 7018.5,7364.16 7049,7364.16 7065.96,7381.12 7102.46,7381.12 7107.5,7386.16 7119,7386.16 7131,7374.16 7197.49,7374.16 7205,7381.67 7205,7394.16 ; 6961,7388.16 6981.5,7408.66 7069.5,7408.66 7073.5,7412.66 ; 6965.66,7174.1 6965.66,7277.16 6981.66,7293.16 7063,7293.16 7070,7286.16 7239.5,7286.16 7285.04,7331.7 7346.81,7331.7 7365.23,7350.12 7440.96,7350.12 7450,7359.16 7450.5,7359.16 ; 6965.66,7774.1 7047,7692.76 7047,7605.66 ; 6978,7386.26 6979.4,7387.66 6979.5,7387.66 6990,7398.16 7077.5,7398.16 7090.97,7411.62 ; 7015.66,7124.1 7015.66,7265.81 7028.5,7278.66 7240.9,7278.66 7253.15,7290.91 7306.95,7290.91 7310.66,7294.62 7373.46,7294.62 7378.4,7299.56 7399.87,7299.56 7400.33,7300.02 ; 7015.66,7824.1 7015.66,7777.5 7046,7747.16 7131.5,7747.16 7153.5,7725.16 7153.5,7609.16 7158.5,7604.16 7158.5,7563.16 7173,7548.66 7173,7484.46 7185.02,7472.44 7208.71,7472.44 7209.5,7471.66 7213,7471.66 ; 7065.66,7174.1 7065.66,7230.31 7090.5,7255.16 7269.5,7255.16 7292,7232.66 7385,7232.66 7388.5,7229.16 ; 7067.5,7308.16 7077.54,7298.12 7106.97,7298.12 7123.51,7314.66 7216,7314.66 7226,7324.66 ; 7081.5,7355.66 7083.04,7354.12 7181.04,7354.12 7188.5,7346.66 7351.5,7346.66 7361,7356.16 7431.5,7356.16 7462.5,7387.16 7470.5,7387.16 ; 7081.5,7451.16 7064,7468.66 7064,7589.66 7073.5,7599.16 7073.5,7667.66 7086.5,7680.66 ; 7084.27,7626.58 7084.58,7626.58 7085,7626.16 7085,7598.16 7070.5,7583.66 7070.5,7478.66 7085.5,7463.66 ; 7084.5,7307.66 7087,7305.16 7104.5,7305.16 7120.5,7321.16 7206.5,7321.16 7222.5,7337.16 7230.5,7337.16 ; 7094.5,7363.66 7106.15,7363.66 7107.15,7362.66 7181.91,7362.66 7185.5,7359.07 7185.5,7358.85 7191.65,7352.7 7200.27,7352.7 ; 7097,7502.66 7091.5,7508.16 7091.5,7603.16 7109.5,7621.16 7109.5,7671.16 7104,7676.66 ; 7115.66,7824.1 7115.66,7776.5 7161,7731.16 7161,7615.16 7183,7593.16 7183,7489.66 7183.5,7489.16 ; 7126,7736.16 7126,7534.66 7135,7525.66 7135,7511.66 7136.5,7510.16 ; 7140,7721.66 7145.5,7716.16 7145.5,7605.66 7147.6,7603.56 7147.6,7521.61 7147.5,7521.51 7147.5,7512.81 7147.6,7512.71 7147.6,7508.56 7150,7506.16 ; 7153,7439.66 7165.46,7452.12 7323.96,7452.12 7402,7530.16 7402,7650.66 7440,7688.66 7549.5,7688.66 ; 7165.66,7174.1 7165.66,7226.81 7185,7246.16 7261.5,7246.16 7287,7220.66 7347,7220.66 ; 7165.66,7774.1 7170.4,7769.36 7170.4,7678.76 7172,7677.16 ; 7200.31,7352.66 7329,7352.66 7343.21,7366.87 7344.12,7367.76 7365.09,7367.76 7368.2,7364.66 7423.8,7364.66 7435.94,7376.8 7436.42,7376.8 ; 7202.54,7496.16 7257,7496.16 7285.99,7525.15 7285.99,7745.15 7315.66,7774.81 7315.66,7824.1 ; 7204.36,7461.94 7303.78,7461.94 7316,7474.16 7334,7474.16 7394.5,7534.66 7394.5,7658.5 7515.66,7779.66 7515.66,7824.1 ; 7215.66,7124.1 7215.66,7167.31 7258.5,7210.16 7404,7210.16 7418.5,7224.66 ; 7218.7,7677.46 7217.59,7676.35 7217.59,7645.57 7277,7586.16 7277,7532.24 7275.31,7530.55 ; 7227,7301.16 7227.5,7301.66 7236.5,7301.66 ; 7239.25,7364.41 7239.5,7364.16 7331,7364.16 7372,7405.16 7464.5,7405.16 7465,7404.66 ; 7241,7382.16 7250,7373.16 7330.5,7373.16 7368.5,7411.16 7452,7411.16 7455.5,7414.66 ; 7301.65,7312.64 7304.52,7312.64 7307.5,7309.66 7307.5,7303.66 ; 7315,7283.66 7318.5,7287.16 7342.5,7287.16 7354.8,7274.86 7386.7,7274.86 7392.5,7280.66 ; 7326.38,7265.28 7329.5,7262.16 7466,7262.16 7469.5,7265.66 ; 7331.5,7245.66 7340,7254.16 7480,7254.16 7482.5,7256.66 ; 7337.42,7274.74 7343.7,7268.46 7398.44,7268.46 7408.5,7278.52 7408.5,7288.16 ; 7385.5,7421.66 7386.5,7422.66 7395.5,7422.66
  L4.Cu w8: 7216.5,7363.16 7216.5,7377.18 7255.97,7416.66 7361.98,7416.66 7364.98,7419.66 7365.1,7419.66 7430.1,7484.66 7431.38,7484.66 7481,7534.27 7481,7535.66
  L4.Cu w10: 6994.5,7418.66 7056.5,7418.66 7064.5,7426.66 7097.5,7426.66 7140,7384.16 7192.4,7384.16 7193.7,7385.46
  L4.Cu w12: 7272.5,7638.66 7262.5,7638.66 7251.5,7649.66 7251.5,7679.16 7272,7699.66 7272.5,7699.66
  Bottom Layer w3: 6901.57,7642.44 6924.29,7642.44 6950.96,7669.12 6985.54,7669.12 7001,7653.66 7026.5,7653.66 7035,7645.16 ; 6901.57,7701.58 6923.58,7701.58 6950,7675.16 6989,7675.16 7004,7660.16 7023.4,7660.16 7035.9,7672.66 ; 7239.5,7525.66 7243.5,7521.66 7243.5,7521.31 7249.65,7515.16 7258.35,7515.16 7268.5,7525.31 7268.5,7587.15 7308.5,7627.15 7308.5,7628.51 7314.65,7634.66 7316.01,7634.66 7317.51,7636.16 7377.96,7636.16 7417.72,7675.91 ; 7254,7525.66 7261.5,7533.16 7261.5,7595.16 7290.5,7624.16 7290.5,7648.69 7317.72,7675.91 ; 7307.5,7303.66 7307.5,7302.16 7317.72,7291.94 7317.72,7275.52 ; 7308.27,7522.76 7308.27,7476.39 7320,7464.66 7320.17,7464.66 ; 7348.47,7357.26 7356.37,7365.16 7413.5,7365.16 7445.5,7397.16 7445.5,7459.99 7508.27,7522.76 7433.37,7597.66 7420.5,7597.66 ; 7359.5,7441.16 7363.5,7441.16 7408.27,7485.93 7408.27,7522.76 ; 7455.5,7415.16 7455.5,7457.66 7487,7489.16 7574.67,7489.16 7608.27,7522.76 ; 7465,7404.66 7465,7451.16 7491,7477.16 7553.87,7477.16 7607.87,7423.15
  Bottom Layer w10: 7036,7487.66 7048,7487.66
  Bottom Layer w12: 7036,7487.66 7036,7500.66 7047.28,7511.93 7071.65,7511.93 7064.78,7511.93 7044.32,7491.48 7043.64,7491.48
  other v1: 3621.7,10801.7 4358.2,10805.2 4133.2,10813.2 3712.2,10814.7 3746.7,10823.7 4328.2,10828.2 4223.7,10829.2 4148.2,10831.7 3633.2,10833.2 3702.7,10833.2 3594.2,10833.7 4200.2,10835.7 3861.2,10839.2 3763.2,10839.7 3813.2,10840.2 3843.7,10840.2 4170.2,10839.7 3796.2,10840.7 3660.2,10845.2 3743.2,10849.7 4359.2,10849.7 3702.2,10856.2 4093.2,10865.2 3995.2,10881.7 3720.58,10894.08 3666.7,10901.2 3972.2,10902.45 3720.78,10904.7 4093.7,10907.7 3839.7,10922 3732.2,10925.7 3895.2,10926.2 3643.2,10926.7 3721.9,10926.6 4073.7,10929.7 4084.7,10931.2 3668.2,10934.2 3815.7,10937.7 4046.98,10940.49 4076.37,10940.24 4088.88,10940.69 4317.7,10941.7 4036.58,10944.24 3720.7,10946.2 3975.2,10945.7 3742.2,10948.2 3815.7,10949.2 3839.7,10953.2 3892.2,10952.7 3911.2,10953.2 4077.4,10954.3 4255.7,10956.7 3921.2,10959.2 3817.7,10960.7 4085.2,10962.2 3586.2,10964.2 4352.1,10964.49 3892.2,10965.7 4296.2,10968.2 4063.17,10979.31 3910.7,10985.24 3931.2,10985.2 3953.95,10986.45 3826.2,10995.2 4106.7,10998.45 4322.7,10999.2 3955.7,11004.2 3586.7,11005.2 3741.2,11005.2 4368.7,11006.2 3765.7,11007.2 3908.4,11007.5 4092.6,11011.9 3809.2,11012.7 4104.2,11016.96 3614.2,11020.7 4057.45,11021.95 3976.42,11023.42 4364.7,11036.7 3586.2,11039.2 3631.7,11039.7 3930.7,11044.2 3843.7,11045.2 3888.2,11045.7 3745.2,11054.7 3695.2,11058.2 3661.2,11058.7 3611.2,11060.7 3867.7,11061.7 3923.2,11062.7 4074.2,11063.2 3974.1,11064.09 3995.36,11063.95 3585.2,11066.7 4375.2,11067.7 4072.45,11083.2 4034.87,11086.7 3847.7,11092.2 3859.2,11092.2 3694.7,11094.2 4332.6,11094.41 3739.2,11100.2 3813.8,11102.2 3847.7,11103.45 3859.2,11103.2 3803.85,11105.98 3750.7,11109.7 3762.7,11109.7 4049.7,11115 4140.7,11119.7 4355.2,11122.2 4052.11,11135.83 3736.7,11138.2 3872.7,11139.2 3687.7,11141.2 3954.2,11147.7 3968.7,11147.7 4375.7,11148.7 3953.65,11160.69 3873.7,11161.7 3965.7,11161.93 3674.2,11163.2 3851.7,11162.7 3736.7,11164.2 3761.17,11164.41 3795.7,11163.8 3817.4,11163.8 3587.7,11164.7 3620.2,11174.7 3954.32,11175.7 3965.2,11175.7 4346.7,11180.7 3691.7,11181.7 4135.2,11182.7 3645.7,11183.7 4301.7,11187.7 4095.2,11189.2 3887.1,11191.1 3851.68,11192.84 3594.2,11194.2 3738.7,11194.2 3796.2,11194.7 3824.2,11194.7 4092.8,11201.4 3666.2,11202.2 3625.2,11204.2 3691.2,11209.7 4322.7,11211.7 4135.2,11219.7 4363.91,11220.4 4272.2,11221.7 4062.7,11223.7 4192.06,11224.54 3898.2,11230.7 3586.7,11233.7 3983.66,11240.43 4302.7,11242.7 4033.7,11246.2 3812.2,11253.2 3773.11,11255.17 3987.2,11260.7 4018.52,11260.98 3749.7,11267.2 3693.7,11267.7 4163.2,11267.7 3900.7,11269.2 3683.2,11278.2 3981.47,11279.54 4192.2,11292.7 3750.6,11294.7 3818.7,11298.7 3987.2,11298.7 3933.4,11299.5 4084.7,11306.2 3692.7,11308.7 4264.2,11310.7 3720.2,11315.2 3897.2,11320.7 3682.2,11322.2 3987.2,11321.7 3797.7,11323.2 3768.2,11324.7 4246.2,11330.7 4361.7,11332.7 4092.7,11334.2 4316.7,11333.7 3702.7,11335.7 4337.2,11346.7 3903.2,11347.7 3803.2,11349.2 3823.7,11349.2 4207.7,11349.2 3967.7,11349.7 4102.2,11350.2 3760.7,11351.2 3683.7,11353.2 3584.2,11360.2 3616.2,11359.7 3655.7,11359.7 4161.2,11360.2 4244.2,11360.7 4314.7,11362.7 4130.2,11365.2 3731.2,11368.7 4360.2,11369.2 3635.2,11372.7 3600.2,11377.7 4333.2,11381.7 3631.7,11397.7 3601.7,11402.7
  other v2: 4264.2,10847.7 4294.7,10848.2 3816.2,10866.2 4034.2,10865.7 4077.2,10870.7 3625.7,10873.7 4294.2,10877.2 4073.7,10886.2 4264.5,10896.6 3686.2,10902.02 3810.7,10902.7 4033.7,10903.2 4072.7,10907.7 3810.7,10911.7 3991.7,10924.2 3617.2,10941.2 3995.2,10965.7 3975.2,10985.2 3994.82,10985.02 4073.7,10988.2 4057.2,10990.7 4054.32,11002.83 3995.7,11008.2 4127.7,11017.73 4140.7,11021.7 3888.2,11025.7 3953.2,11025.7 3764.95,11028.7 3809.2,11028.7 3843.66,11028.77 4119.7,11029.7 4057.7,11037.7 3826.34,11045.26 4117.7,11055.7 4138.7,11064.7 3940.6,11094.1 3913.2,11107.2 3995.7,11106.7 4009.2,11106.7 3913.2,11120.7 3940.7,11120.7 3954.32,11120.59 3968.2,11120.7 3981.7,11120.7 3995.7,11120.7 4023.2,11120.7 4117.7,11120.7 4009.7,11134.2 4023.21,11134.37 4141.7,11142.7 3995.7,11148.2 4009.43,11148.15 3940.7,11162.2 3995.7,11162.2 4051.7,11161.7 3982.2,11175.7 3995.7,11175.7 3933.7,11189.2 3954.32,11189.48 3981.88,11189.48 3924.06,11200.89 3912.98,11203.26 3954.32,11203.26 3968.1,11203.26 3981.88,11203.26 3940.54,11217.04 3954.32,11217.04 3981.88,11217.04 3995.66,11217.04 3719.7,11254.7 4135.2,11282.2 3719.7,11294.2 3651.7,11303.2 3605.2,11303.7 4012.7,11315.2 4056.7,11315.7
  other v3: 4062.2,10842.7 4133.2,10846.7 4103.2,10851.2 4046.2,10867.7 4197.2,10878.7 4041.08,10887.33 4184.2,10887.7 4052.11,10896.79 4029.7,10905.7 4123.2,10910.2 4115.03,10922.06 3951.2,10923.7 3782.2,10930.2 3799.2,10929.7 4016.35,10934.69 3940.7,10946.7 3945.2,10959.2 3796.2,10977.7 4165.2,10981.2 3658.7,10986.2 3809.2,10985.7 4151.11,10998.85 3692.7,11008.3 4185.2,11009.2 3675.7,11010.2 3919.7,11016.2 3805.67,11033.74 3788.2,11034.7 3709.2,11040.7 4100.2,11043.7 3796.2,11073.2 3919.06,11083.99 3800.2,11085.7 3927.7,11093.7 3898.2,11111.2 3917.2,11118.16 3811.7,11124.7 3864.7,11128.2 3851.2,11132.2 3990.01,11152.59 4195.7,11157.7 3761.7,11227.7 3798.97,11248.63 3886.7,11299.2 3801.2,11302.7 3854.7,11343.7 3840.7,11358.2
  other v4: 4046.2,10857.7 4053.2,10886.54 4053.02,10909.76 4162.2,10911.7 3954,10946.2 3955.2,10965.2 3732.5,10969.7 3745.2,10971.7 3717.7,10981.7 3790.7,10995.7 3809.2,10995.7 3659.2,11000.7 3681.2,11001.2 3700.7,11001.2 3637.2,11019.7 3702.7,11019.7 3735.2,11040.2 4201.2,11084.7 3926.73,11106.68 3899.2,11120.7 3926.7,11120.7 4009.7,11120.7 4201.2,11123.7 3926.2,11132.9 3913.2,11134.2 3940.2,11134.2 3954.2,11134.2 3968.2,11134.2 3981.7,11134.2 3995.7,11134.2 3898.95,11145.99 3926.7,11145.7 3913.3,11147.1 3981.7,11148.2 3982.2,11161.7 3926.76,11163.2 3926.76,11175.7 3940.7,11175.7 3915.76,11178.43 3968.1,11189.48 3803.7,11266.2 3791.7,11302.7 4135.2,11306.7
  other v5: 4072.96,11049.97 3809.7,11073.2 3810.2,11085.7 3815.7,11115.2 3870.16,11118.26 3857.4,11140.21 3841.7,11140.7 4036.7,11194.2 4023.2,11194.7 4050.2,11194.7 3747.69,11205.19 4088.4,11223.9 4046.7,11225.09 4075.52,11225.84 3742.7,11235.2 4092.2,11236.2 3747.7,11247.7 4092.2,11248.7 3738.2,11270.7 3738.2,11283.2
  other v6: 4107.2,10902.7 3941.7,10923.2 4022.2,10925.7 4179.7,11026.7 4170.2,11036.7 4110.2,11044.7

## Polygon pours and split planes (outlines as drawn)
no net on Top Layer (solid, remove dead copper, pour order 2): 3868.7,10916.7 3873.2,10916.7 3876.7,10913.2 3876.7,10894.7 3867.7,10885.7 3867.7,10860.7 3863.2,10856.2 3841.7,10856.2 3836.7,10861.2 3836.7,10890.2 3851.2,10904.7 3859.7,10904.7 3865.2,10910.2 3865.2,10913.2
no net on Top Layer (solid, remove dead copper, pour order 4): 3940.38,10856.7 3894.2,10856.7 3888.7,10862.2 3888.7,10891.7 3881.2,10899.2 3881.2,10913.7 3884.7,10917.2 3932.2,10917.2 3941.7,10907.7 3953.2,10907.7 3960.64,10899.97 3960.64,10874.14 3957.87,10871.19 3945.01,10871.19 3944.59,10870.76 3944.59,10860.92
no net on Top Layer (solid, remove dead copper, pour order 6): 3874.9,10931.41 3874.9,10925.2 3872.4,10922.7 3868.2,10922.7 3865.2,10925.7 3865.2,10942.7 3866.7,10944.2 3866.7,10963.7 3874.7,10971.7 3895.7,10971.7 3899.2,10968.2 3899.2,10943.2 3894.7,10938.7 3882.2,10938.7
no net on Top Layer (solid, remove dead copper, pour order 8): 4091.2,10945.7 4103.7,10933.2 4103.7,10927.51 4099.4,10923.2 4092.7,10923.2 4086.7,10917.2 4069.2,10917.2 4065.2,10921.2 4065.2,10936.7 4074.2,10945.7
no net on Top Layer (solid, remove dead copper, pour order 10): 3938.14,10871.2 3983.2,10871.2 3986.7,10867.7 3986.7,10858.7 3992.2,10853.2 4037.7,10853.2 4103.2,10787.7 4103.2,10779.2 4095.2,10771.2 4057.2,10771.2 4008.7,10819.7 3977.2,10819.7 3935.17,10861.73 3935.17,10868.23
no net on Top Layer (solid, remove dead copper, pour order 12): 3813.7,11077.7 3811.7,11075.7 3803.7,11075.7 3801.7,11077.7 3801.7,11080.7 3796.7,11085.7 3780.7,11085.7 3775.7,11090.7 3775.7,11099.7 3771.7,11103.7 3748.7,11103.7 3745.7,11106.7 3745.7,11117.7 3748.7,11120.7 3784.7,11120.7 3787.7,11117.7 3787.7,11110.7 3813.7,11084.7
no net on Top Layer (solid, remove dead copper, pour order 14): 4145.2,11011.2 4199.7,11011.2 4204.2,11006.7 4204.2,10992.7 4199.7,10988.2 4152.7,10988.2 4124.7,10960.2 4124.7,10928.7 4120.7,10924.7 4111.7,10924.7 4110.2,10926.2 4110.2,10932.7 4096.2,10946.7 4096.2,10977.7 4112.2,10993.7 4112.2,10998.7 4116.7,11003.2 4137.2,11003.2
no net on Top Layer (solid, remove dead copper, pour order 16): 3831.2,10981.7 3831.2,10936.7 3826.2,10931.7 3810.7,10931.7 3806.7,10935.7 3806.7,10957.2 3819.2,10969.7 3819.2,10981.7 3821.7,10984.2 3828.7,10984.2
no net on Top Layer (solid, remove dead copper, pour order 18): 3838.7,11094.2 3841.7,11097.2 3841.7,11105.2 3844.7,11108.2 3862.2,11108.2 3865.7,11104.7 3865.7,11092.7 3852.2,11079.2 3852.2,11061.2 3849.2,11058.2 3841.7,11058.2 3838.7,11061.2
no net on Top Layer (solid, remove dead copper, pour order 20): 3830.7,11093.7 3830.7,11061.7 3827.2,11058.2 3823.2,11058.2 3819.7,11061.7 3819.7,11084.7 3796.2,11108.2 3796.2,11116.7 3798.7,11119.2 3813.7,11119.2 3824.2,11108.7 3830.2,11108.7 3834.2,11104.7 3834.2,11097.2
no net on Bottom Layer (solid, remove dead copper, pour order 46): 4108.7,10968.7 4108.7,10792.2 4090.7,10774.2 4070.7,10774.2 4025.2,10819.7 3999.7,10819.7 3966.2,10853.2 3966.2,11020.7 4010.2,11064.7 4037.2,11064.7 4045.2,11056.7 4045.2,10990.2 4055.7,10979.7 4097.7,10979.7
no net on L4.Cu (solid, remove dead copper): 4078.2,10945.7 4099.2,10966.7 4215.2,10966.7 4308.2,10873.7 4308.2,10784.2 4294.2,10770.2 4265.2,10770.2 4251.7,10783.7 4251.7,10842.2 4166.7,10927.2 4094.7,10927.2 4087.7,10920.2 4068.7,10920.2 4063.7,10925.2 4063.7,10940.7 4068.7,10945.7
no net on L5.Cu (solid, remove dead copper): 4106.7,11016.2 4106.7,10934.2 4082.2,10909.7 4014.7,10909.7 4002.2,10922.2 4002.2,11007.7 3941.7,11068.2 3842.7,11068.2 3834.7,11076.2 3834.7,11107.7 3844.7,11117.7 4005.2,11117.7
no net on L5.Cu (solid, remove dead copper): 3822.7,11110.7 3822.7,11075.2 3842.2,11055.7 3902.2,11055.7 3938.7,11019.2 3938.7,10940.7 3929.2,10931.2 3789.7,10931.2 3779.7,10941.2 3779.7,11108.7 3787.2,11116.2 3817.2,11116.2
no net on Top Layer (solid, remove dead copper, pour order 30): 4258.7,10988.7 4157.7,10988.7 4153.2,10993.2 4153.2,11007.2 4157.7,11011.7 4218.7,11011.7 4230.7,11023.7 4230.7,11163.7 4217.2,11177.2 4156.7,11177.2 4153.7,11180.2 4153.7,11196.2 4157.7,11200.2 4261.2,11200.2 4280.2,11181.2 4280.2,11010.2
no net on L5.Cu (solid, remove dead copper): 3980.2,10859.2 3962.2,10877.2 3702.7,10877.2 3675.2,10904.7 3675.2,11141.7 3865.2,11331.7 3949.7,11331.7 3971.2,11310.2 4120.7,11310.2 4160.2,11270.7 4160.2,10885.2 4134.2,10859.2
no net on Top Layer (solid, remove dead copper, pour order 34): 3635.7,11440.7 4333.7,11440.7 4338.7,11439.7 4349.7,11435.7 4359.7,11429.7 4372.7,11420.7 4381.7,11410.7 4386.7,11400.7 4390.7,11391.7 4394.7,11379.7 4394.7,10813.7 4390.7,10800.7 4381.7,10782.7 4368.7,10767.7 4344.7,10752.7 4328.7,10747.7 3575.7,10747.7 3575.7,11133.3 3575.7,11377.7 3579.7,11389.7 3588.7,11409.7 3608.7,11428.7
no net on Bottom Layer (solid, remove dead copper, pour order 60): 3635.7,11440.7 4333.7,11440.7 4338.7,11439.7 4349.7,11435.7 4359.7,11429.7 4372.7,11420.7 4381.7,11410.7 4386.7,11400.7 4390.7,11391.7 4394.7,11379.7 4394.7,10813.7 4390.7,10800.7 4381.7,10782.7 4368.7,10767.7 4344.7,10752.7 4328.7,10747.7 3575.7,10747.7 3575.7,11133.3 3575.7,11377.7 3579.7,11389.7 3588.7,11409.7 3608.7,11428.7
no net on L2.Cu (solid, remove dead copper): 3635.7,11440.7 4333.7,11440.7 4338.7,11439.7 4349.7,11435.7 4359.7,11429.7 4372.7,11420.7 4381.7,11410.7 4386.7,11400.7 4390.7,11391.7 4394.7,11379.7 4394.7,10813.7 4390.7,10800.7 4381.7,10782.7 4368.7,10767.7 4344.7,10752.7 4328.7,10747.7 3575.7,10747.7 3575.7,11133.3 3575.7,11377.7 3579.7,11389.7 3588.7,11409.7 3608.7,11428.7
no net on L3.Cu (solid, remove dead copper): 3635.7,11440.7 4333.7,11440.7 4338.7,11439.7 4349.7,11435.7 4359.7,11429.7 4372.7,11420.7 4381.7,11410.7 4386.7,11400.7 4390.7,11391.7 4394.7,11379.7 4394.7,10813.7 4390.7,10800.7 4381.7,10782.7 4368.7,10767.7 4344.7,10752.7 4328.7,10747.7 3575.7,10747.7 3575.7,11133.3 3575.7,11377.7 3579.7,11389.7 3588.7,11409.7 3608.7,11428.7
no net on L4.Cu (solid, remove dead copper): 3635.7,11440.7 4333.7,11440.7 4338.7,11439.7 4349.7,11435.7 4359.7,11429.7 4372.7,11420.7 4381.7,11410.7 4386.7,11400.7 4390.7,11391.7 4394.7,11379.7 4394.7,10813.7 4390.7,10800.7 4381.7,10782.7 4368.7,10767.7 4344.7,10752.7 4328.7,10747.7 3575.7,10747.7 3575.7,11133.3 3575.7,11377.7 3579.7,11389.7 3588.7,11409.7 3608.7,11428.7
no net on L5.Cu (solid, remove dead copper): 3635.7,11440.7 4333.7,11440.7 4338.7,11439.7 4349.7,11435.7 4359.7,11429.7 4372.7,11420.7 4381.7,11410.7 4386.7,11400.7 4390.7,11391.7 4394.7,11379.7 4394.7,10813.7 4390.7,10800.7 4381.7,10782.7 4368.7,10767.7 4344.7,10752.7 4328.7,10747.7 3575.7,10747.7 3575.7,11133.3 3575.7,11377.7 3579.7,11389.7 3588.7,11409.7 3608.7,11428.7

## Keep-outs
Top Layer:
  region: 3888.2,10854.7 3866.7,10854.7 3866.7,10856.7 3870.7,10860.7 3884.2,10860.7 3888.2,10856.7
  region: 3977.7,11308.7 3977.7,11290.7 3973.7,11286.7 3945.7,11286.7 3940.2,11292.2 3940.2,11305.2 3943.7,11308.7
Board Outline Layer:
  lines w5.91: 3841.34,10875.91 ccw(c3851.34,10875.91) 3851.34,10865.91 3881.34,10865.91 ccw(c3881.34,10875.91) 3891.34,10875.91 ; 3841.34,10876.11 cw(c3851.34,10876.11) 3851.34,10886.11 ; 3851.54,10886.2 3881.54,10886.2 ; 3881.34,10886.11 cw(c3881.34,10876.11) 3891.34,10876.11 ; 3961.42,11385.16 cw(c3961.42,11395.16) 3951.42,11395.16 cw(c3961.42,11395.16) 3961.42,11405.16 3991.42,11405.16 cw(c3991.42,11395.16) 4001.42,11395.16 cw(c3991.42,11395.16) 3991.42,11385.16 ; 3961.42,11385.36 3991.42,11385.36
  lines w10: 3000,10341.66 3000,11798.35 4393.7,11798.35 4393.7,10341.66 3000,10341.66

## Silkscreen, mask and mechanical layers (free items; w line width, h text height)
Top Silkscreen Layer:
  drawing of 225 lines, arcs and shapes, not listed
  text "R" at 4206.7,11369.95 h35 r270
  text "B" at 4203.7,10841.95 h35 r270
  text "LAYERS LAMINATION & IMPEDANCE CONTROL" at 9602.95,7850.22 h88
  text "IMPEDANCE" at 11602.95,7773.82 h30.8
  text "LAYER" at 9127.95,7693.82 h30.8
  text "MATERIAL" at 9367.95,7693.82 h30.8
  text "THICKNESS" at 9662.95,7693.82 h30.8
  text "LAYER TYPE" at 9987.95,7693.82 h30.8
  text "SINGLE 50ohm+/-10%" at 10577.95,7693.82 h30.8
  text "DIFFERENCE 90ohm+/-10%" at 11552.95,7693.82 h30.8
  text "DIFFERENCE 100ohm+/-10%" at 12577.95,7693.82 h30.8
  text "6 LAYER#- -1.2MM / LAYERS STACKUP" at 8427.95,7640.8 h30.8
  text "Line width(mil)" at 10577.95,7623.82 h30.8
  text "Line width/Space(mil)" at 11552.95,7623.82 h30.8
  text "Line width/Space(mil)" at 12577.95,7623.82 h30.8
  text "TOP" at 8617.95,7548.82 h30.8
  text "TOP" at 9127.95,7548.82 h30.8
  text "COPPER" at 9382.95,7548.82 h30.8
  text "1 OZ" at 9692.95,7548.82 h30.8
  text "ROUTING" at 10037.95,7548.82 h30.8
  text "W:6.16" at 10727.95,7548.82 h30.8
  text "W:5.59/S:6" at 11702.95,7548.82 h30.8
  text "PP" at 8612.95,7473.82 h30.8
  text "PP" at 9382.95,7473.82 h30.8
  text "3.01mil" at 9692.95,7473.82 h30.8
  text "L2 INNER" at 8552.95,7398.82 h30.8
  text "L2 INNER" at 9072.95,7398.82 h30.8
  text "COPPER" at 9382.95,7398.82 h30.8
  text "0.5 OZ" at 9692.95,7398.82 h30.8
  text "ROUTING" at 10037.95,7398.82 h30.8
  text "PP" at 8612.95,7323.82 h30.8
  text "PP" at 9377.95,7323.82 h30.8
  text "3.91mil" at 9692.95,7323.82 h30.8
  text "L3 INNER" at 8552.95,7248.82 h30.8
  text "L3 INNER" at 9072.95,7248.82 h30.8
  text "COPPER" at 9382.95,7248.82 h30.8
  text "0.5 OZ" at 9692.95,7248.82 h30.8
  text "ROUTING" at 10037.95,7248.82 h30.8
  text "PP" at 8612.95,7173.82 h30.8
  text "PP" at 9382.95,7173.82 h30.8
  text "27.8mil" at 9692.95,7173.82 h30.8
  text "L4 INNER" at 8552.95,7098.82 h30.8
  text "L4 INNER" at 9072.95,7098.82 h30.8
  text "COPPER" at 9382.95,7098.82 h30.8
  text "0.5 OZ" at 9692.95,7098.82 h30.8
  text "ROUTING" at 10037.95,7098.82 h30.8
  text "PP" at 8612.95,7023.82 h30.8
  text "PP" at 9377.95,7023.82 h30.8
  text "3.91mil" at 9692.95,7023.82 h30.8
  text "L5 INNER" at 8552.95,6948.82 h30.8
  text "L5 INNER" at 9072.95,6948.82 h30.8
  text "COPPER" at 9382.95,6948.82 h30.8
  text "0.5 OZ" at 9692.95,6948.82 h30.8
  text "ROUTING" at 10037.95,6948.82 h30.8
  text "PP" at 8612.95,6873.82 h30.8
  text "PP" at 9382.95,6873.82 h30.8
  text "3.01mil" at 9692.95,6873.82 h30.8
  text "BOTTOM" at 8567.95,6798.82 h30.8
  text "BOTTOM" at 9102.95,6798.82 h30.8
  text "COPPER" at 9382.95,6798.82 h30.8
  text "1 OZ" at 9692.95,6798.82 h30.8
  text "ROUTING" at 10037.95,6798.82 h30.8
Bottom Silkscreen Layer:
  text "N2" at 3587.53,11341.28 h20 r270
  text "D6" at 3720.21,11328.58 h25
  text "D5" at 3807.61,11328.58 h25
  text "D4" at 3904.07,11328.58 h25
  text "D2" at 4125.33,11328.97 h25
  text "D3" at 4003.28,11328.18 h25
  text "D1" at 4209.19,11324.43 h25
  text "D0" at 4310.37,11324.43 h25
  text "N1" at 3586.75,11189.42 h20 r270
  text "D15" at 3819.82,11181.78 h20 r270
  text "D17" at 4017.85,11181.38 h20 r270
  text "D18" at 4117.7,11181.2 h20 r270
  text "D16" at 3918.64,11179.81 h20 r270
  text "+" at 3768.7,11145.2 h30 r270
  text "RST" at 4256.43,11102.25 h20 r270
  text "RST2" at 4048.41,11089.37 h20 r270
  text "SWDIO2" at 4153.7,11085.24 h20 r270
  text "SWDIO" at 4352.89,11076.67 h20 r270
  text "BAT" at 3830.7,11034.98 h25 r270
  text "-" at 3800.7,11024.2 h30 r90
  text "GND" at 4254.46,11000.28 h20 r270
  text "3V3" at 4049.2,10998.7 h20 r270
  text "SWCLK" at 4353.28,10955.46 h20 r270
  text "SWCLK2" at 4156.2,10944.88 h20 r270
  text "SHPHLD" at 3587.7,10927.7 h20 r270
  text "D14" at 3820.6,10926.66 h20 r270
  text "D13" at 3918.24,10923.9 h20 r270
  text "D12" at 4019.7,10924.2 h20 r270
  text "D11" at 4117.34,10921.45 h20 r270
  text "XIAO nRF54LM20A" at 3644.7,10885.7 h20 r270
  text "D10" at 4037.14,10814.01 h25
  text "D7" at 3719.7,10812.85 h25
  text "D8" at 3805.25,10813.22 h25
  text "D9" at 3895.01,10812.83 h25
  text "3V3" at 4125.7,10813.35 h25
  text "GND" at 4218.24,10813.22 h25
  text "VBUS" at 4331.23,10809.08 h25
  text "GND" at 3589.7,10764.2 h20 r270
Top Solder Mask Layer:
  lines w20: 3693.7,11077.7 3693.7,11046.7 3587.7,11046.7 3587.7,10836.7 3881.2,10836.7 ; 3693.7,11156.7 3693.7,11214.7 ; 3693.7,11258.2 3693.7,11355.45 ; 3693.95,11355.7 3916.2,11355.7 ; 4077.2,10836.7 4163.2,10836.7 4163.2,10885.7 ; 4083.2,11355.7 4162.95,11355.7 4162.95,11280.2
Bottom Solder Mask Layer:
  region: 3967.7,11160.7 3864.7,11160.7 3864.7,11194.7 3967.7,11194.7
  region: 3942.7,11126.7 3883.7,11126.7 3883.7,11160.7 3942.7,11160.7
  region: 3978.7,11057.7 3883.7,11057.7 3883.7,11127.7 3978.7,11127.7
User.1:
  lines w19.68: 3672.09,10836.74 4163.1,10836.54 4163.12,10939.34 ; 3693.7,11355.66 4163.12,11355.66 4163.12,11279.66
  lines w20: 3672.09,10836.74 3587.64,10836.74 3587.64,11046.7 3693.7,11046.7 ; 3693.7,11046.95 3693.7,11355.66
